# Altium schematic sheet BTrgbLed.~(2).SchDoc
size A4
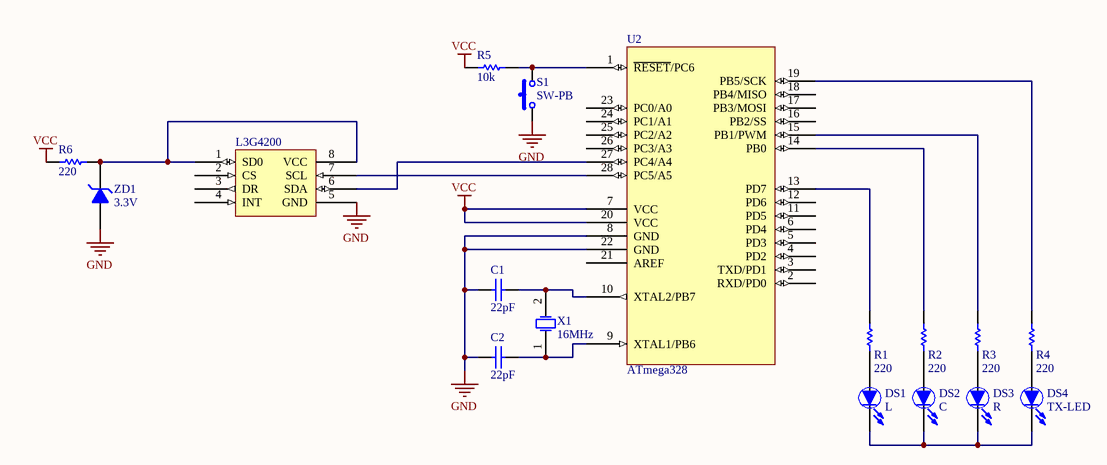
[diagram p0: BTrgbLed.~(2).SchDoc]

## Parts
C1  22pF  [C200]
C2  22pF  [C200]
DS1  L  [LED-3mm_G]
DS2  C  [LED-3mm_G]
DS3  R  [LED-3mm_G]
DS4  TX-LED  [LED-3mm_G]
L3G4200  (no value)  [L3G4200]
R1  220  [AXIAL-0.3]
R2  220  [AXIAL-0.3]
R3  220  [AXIAL-0.3]
R4  220  [AXIAL-0.3]
R5  10k  [AXIAL-0.3]
R6  220  [AXIAL-0.3]
S1  SW-PB  [TACK6]
U2  ATmega328  [DIP28]
X1  16MHz  [XTAL4-8]
ZD1  3.3V  [D400]

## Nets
GND: C1.1 C2.1 L3G4200.5(GND) S1.1 U2.8(GND) U2.22(GND) ZD1.1(A)
VCC: R5.1 R6.1 U2.7(VCC) U2.20(VCC)
NetC1_2: C1.2 U2.10(XTAL2/PB7) X1.2(OSC2)
NetC2_2: C2.2 U2.9(XTAL1/PB6) X1.1(OSC1)
NetDS1_1: DS1.1(A) R1.1
NetDS1_2: DS1.2(K) DS2.2(K) DS3.2(K) DS4.2(K)
NetDS2_1: DS2.1(A) R2.1
NetDS3_1: DS3.1(A) R3.1
NetDS4_1: DS4.1(A) R4.1
NetL3G4200_1: L3G4200.1(SD0) L3G4200.8(VCC) R6.2 ZD1.2(K)
NetL3G4200_6: L3G4200.6(SDA) U2.27(PC4/A4)
NetL3G4200_7: L3G4200.7(SCL) U2.28(PC5/A5)
NetR1_2: R1.2 U2.13(PD7)
NetR2_2: R2.2 U2.14(PB0)
NetR3_2: R3.2 U2.15(PB1/PWM)
NetR4_2: R4.2 U2.19(PB5/SCK)
NetR5_2: R5.2 S1.2 U2.1(~{RESET}/PC6)

Not connected (* = marked no-connect by the designer): L3G4200 2(CS) 3(DR) 4(INT); U2 2(RXD/PD0) 3(TXD/PD1) 4(PD2) 5(PD3) 6(PD4) 11(PD5) 12(PD6) 16(PB2/SS) 17(PB3/MOSI) 18(PB4/MISO) 21(AREF) 23(PC0/A0) 24(PC1/A1) 25(PC2/A2) 26(PC3/A3)

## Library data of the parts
C1 C2 = Cap: Capacitor
DS1-DS4 = LED: Typical INFRARED GaAs LED
L3G4200 = L3G4200: L3G4200ªûÁ³»ö
R1-R6 = Res: Resistor
S1 = SW-PB: Switch
U2 = ATmega328: ATmega¨t¦C³æ´¹¤ù
X1 = XTAL: Crystal Oscillator
ZD1 = Zener Diode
